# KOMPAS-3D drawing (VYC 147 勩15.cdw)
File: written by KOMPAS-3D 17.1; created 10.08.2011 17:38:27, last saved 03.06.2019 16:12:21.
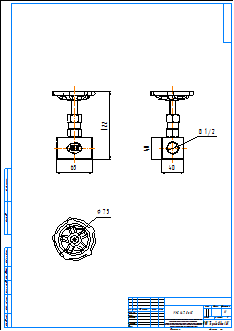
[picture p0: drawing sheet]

Sheet 1: A2, portrait

Title block, sheet 1: name: VYC 147 Ду15; material: Внимание! Данный продукт является объектом авторского права ООО «Торговый Дом АДЛ». / Запрещается изменение, копирование, распространение / (в том числе путем копирования на другие сайты и ресурсы в Интернете) / или любое иное использование информации и объектов без предварительного / согласия правообладателя (ООО «Торговый Дом АДЛ»).; scale: 1:1; sheets: 1; organisation: ООО "Торговый дом АДЛ"; sheet format: A2; stored path: \\adlc.lan\data\АДЛ_ПКД\3D-модели\Поставщики\VYC Industrial\VYC 147\KOMPAS 2D\VYC 147 Ду15.cdw

Views: Спереди 1, Проекционный вид 2, Проекционный вид 3
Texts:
  bsv
  adl
Dimensions and other numbers on the sheet: 65; 40; 122; 75; 1/2; 1:1; 1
